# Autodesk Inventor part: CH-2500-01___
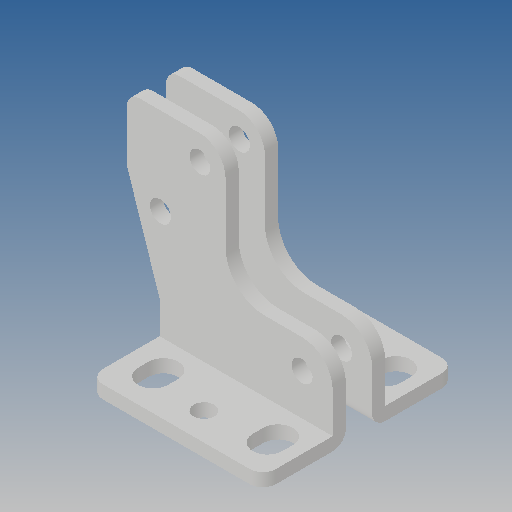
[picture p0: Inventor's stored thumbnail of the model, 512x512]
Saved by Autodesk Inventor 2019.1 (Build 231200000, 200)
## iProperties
Created: 2012-09
Part Number: CH-2500-01___
Material: Ogólny
Document SubType Name: Modeling
Designer: CADENGINEERING4
Density: 1 g/cm^3
Appearance: Domyślna
Author: CADENGINEERING4
Revision Number: ÈÎºÎ
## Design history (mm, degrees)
feature "NONE" [ÊäÈë]
feature "ÊäÈë2"
node "Bryła1"
node "Bryła2"
